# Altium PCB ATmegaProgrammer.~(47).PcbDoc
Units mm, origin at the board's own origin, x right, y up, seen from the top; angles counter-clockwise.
Board outline 54.1 x 69.09 mm, 2 copper layers (Top Layer, Bottom Layer); 9 components, 8 nets, 64 pads, 4 vias.
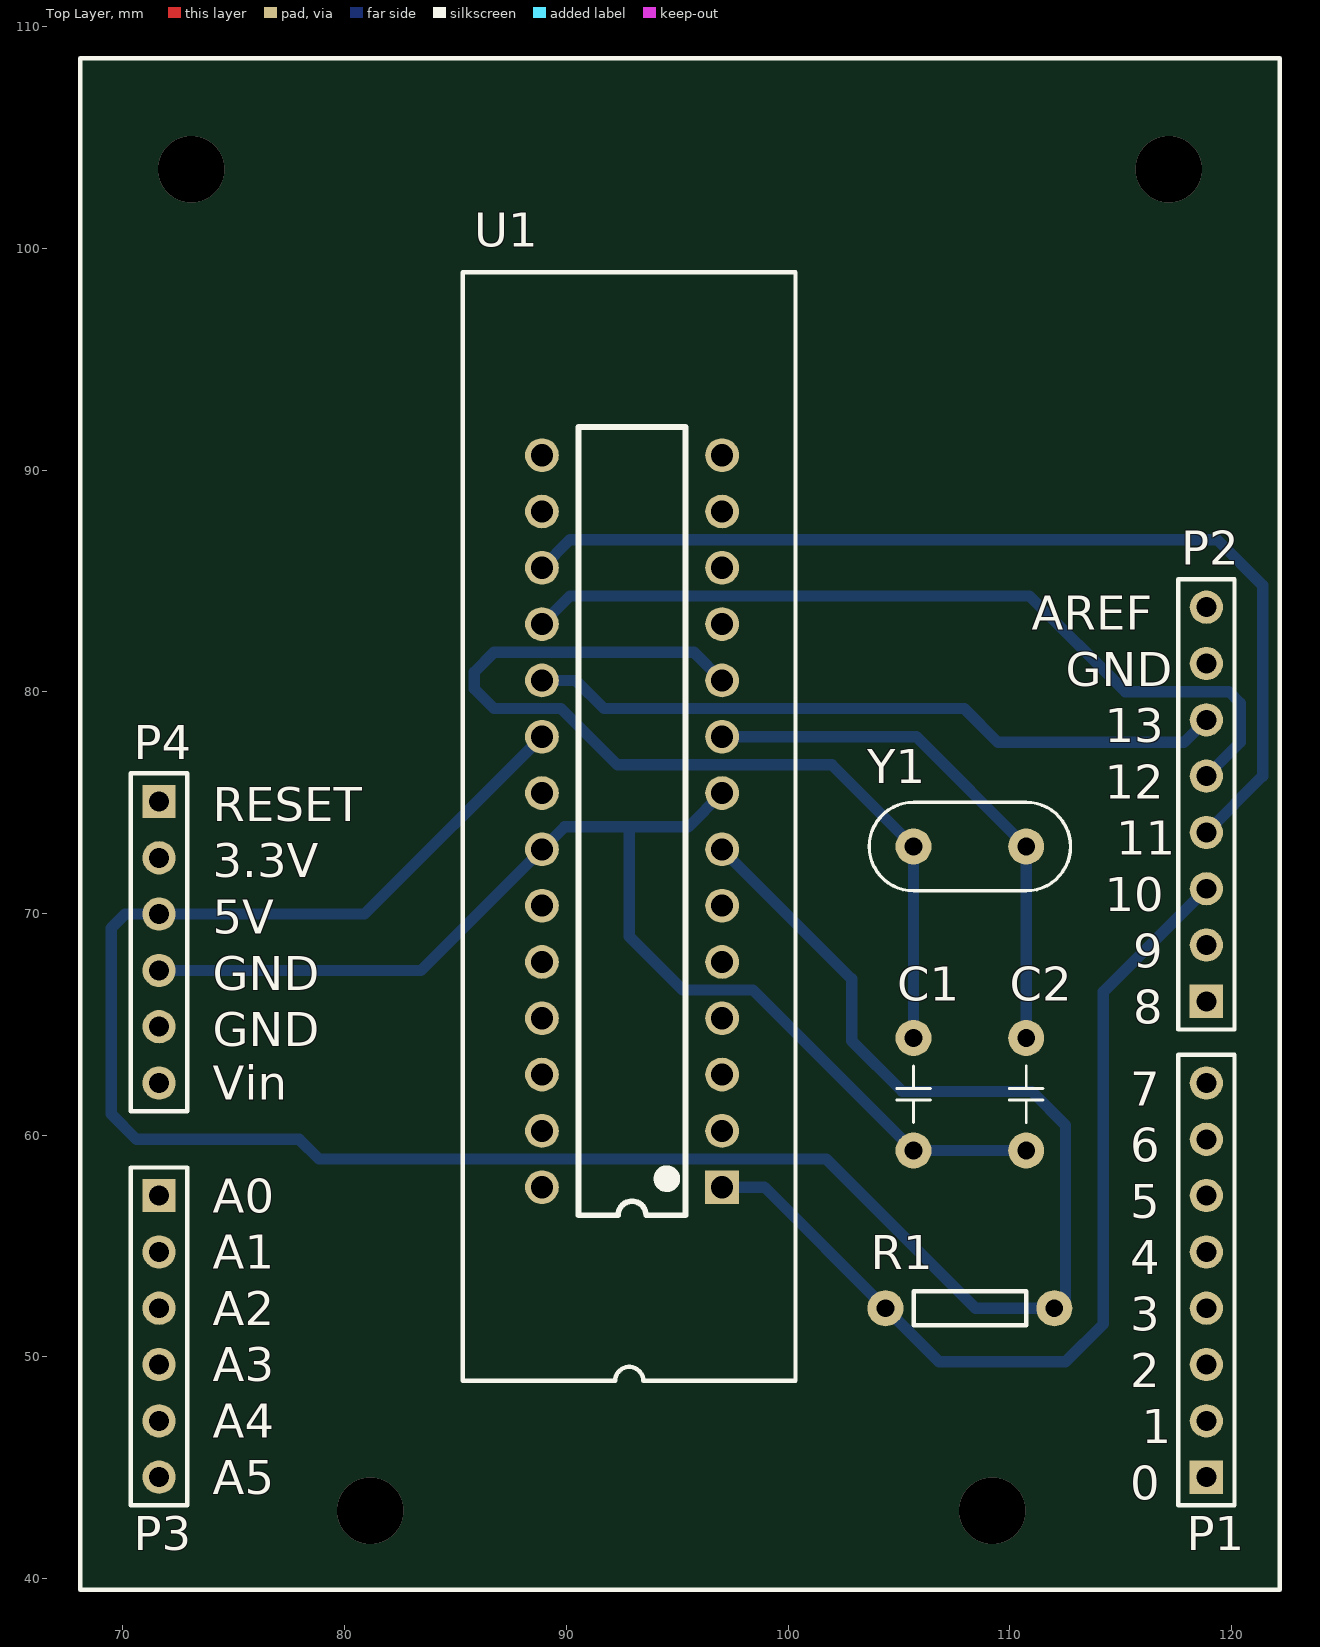
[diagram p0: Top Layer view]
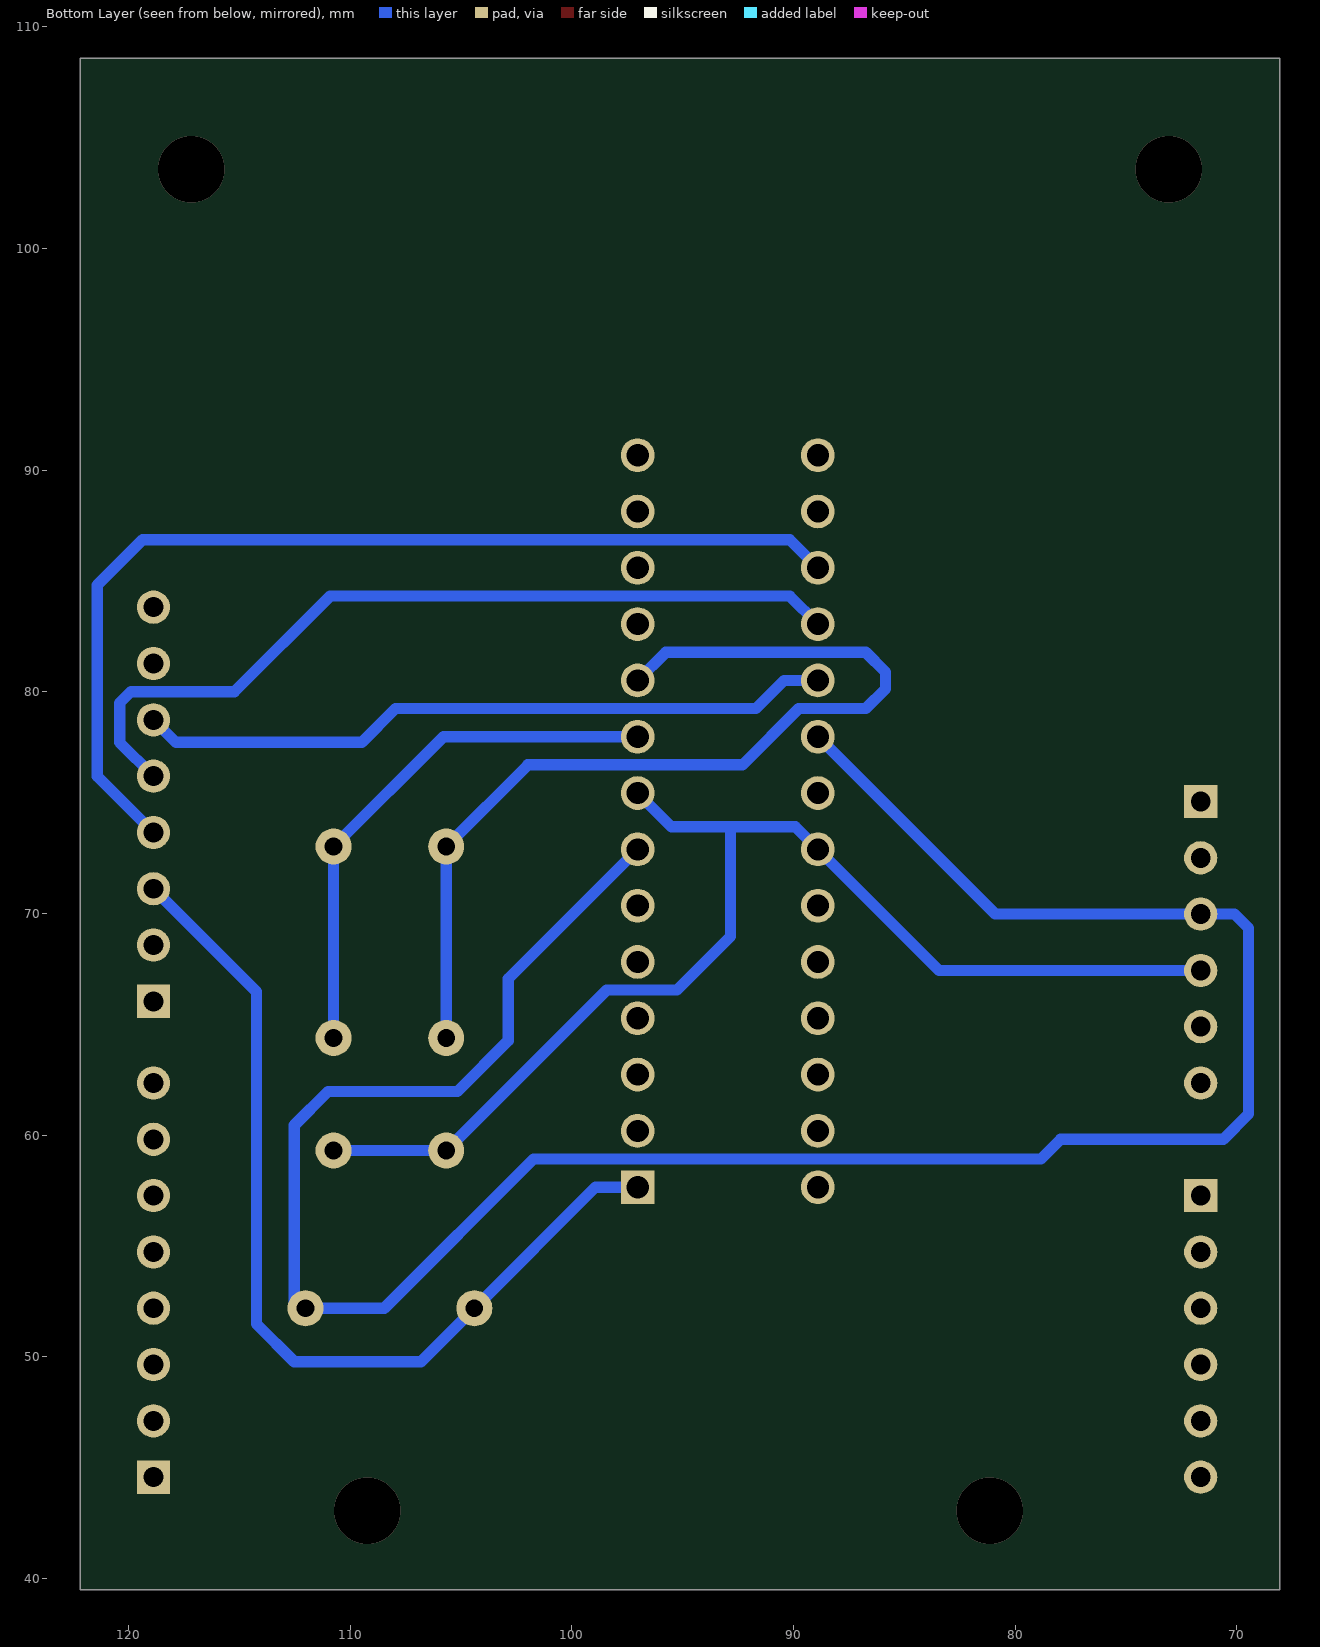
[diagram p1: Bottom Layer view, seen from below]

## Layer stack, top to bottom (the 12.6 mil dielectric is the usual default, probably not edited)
Top Layer: signal copper 0.0356
Dielectric: dielectric 0.32, FR-4, Dk 4.8
Bottom Layer: signal copper 0.0356

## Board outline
68.072,39.497 122.174,39.497 122.174,108.585 68.072,108.585

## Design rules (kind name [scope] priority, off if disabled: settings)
Clearance [All] p1: gap=0.254
PolygonConnect [All] p1: connectstyle=Relief reliefconductorwidth=0.254 reliefentries=4 polygonreliefangle="90 Angle"
RoutingLayers [All] p1: top layer_v5=FALSE bottom layer_v5=TRUE
RoutingVias [All] p1: holewidth=0.711 width=1.27 viastyle="Through Hole" minholewidth=0.711 minwidth=1.27 maxholewidth=0.711 maxwidth=1.27
SilkscreenOverComponentPads [All] p1: minsilkscreentomaskgap=0.254
SolderMaskExpansion [All] p1: expansion=0.102
Width [All] p1: maxlimit=1.016 minlimit=0.254 preferedwidth=0.508
26 further rules are at their usual default settings.

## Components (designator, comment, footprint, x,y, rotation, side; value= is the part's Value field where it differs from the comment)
C1 "20pF" C200 105.664,61.849 r180 top
C2 "20pF" C200 110.744,61.849 r180 top
P1 "Header 8" HDR1X8 118.872,44.577 r90 top
P2 "Header 8" HDR1X8 118.872,66.04 r90 top
P3 "Header 6" HDR1X6 71.628,57.277 r270 top
P4 "Header 6" HDR1X6 71.628,75.057 r270 top
R1 "10k" AXIAL-0.3 108.204,52.197 r0 top
U1 "ATmega328" "DIP28  socket" 92.964,72.136 r180 top
Y1 "16MHz" XTAL4-8 108.204,73.025 r180 top

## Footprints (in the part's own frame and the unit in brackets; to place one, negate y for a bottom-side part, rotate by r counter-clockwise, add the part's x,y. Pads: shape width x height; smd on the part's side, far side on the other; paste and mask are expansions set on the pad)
AXIAL-0.3 [mil] "0.3\" Resistor; 2 Leads"
  round 64 hole 31.5: 1(-150,0) 2(150,0)
  silkscreen extent -100,-30 100,30, body extent -161,-39 165,39, height 86
C200 [mil] "鹅溅筿甧竟"
  round 64 hole 31.5: 1(0,100) 2(0,-100)
  silkscreen extent -30,-50 30,50, body extent -41,-136 39,135, height 354
"DIP28  socket" [mil] "DIP, 28-Pin,Pitch 2.54 mm"
  rect 60x60 hole 39.37: 1(-160,570)
  round 60 hole 39.37: 2(-160,470) 3(-160,370) 4(-160,270) 5(-160,170) 6(-160,70) 7(-160,-30) 8(-160,-130) 9(-160,-230) 10(-160,-330) 11(-160,-430) 12(-160,-530) 13(-160,-630) 14(-160,-730) 15(160,-730) 16(160,-630) 17(160,-530) 18(160,-430) 19(160,-330) 20(160,-230) 21(160,-130) 22(160,-30) 23(160,70) 24(160,170) 25(160,270) 26(160,370) 27(160,470) 28(160,570)
  silkscreen extent -290,-1055 300,914, body extent -290,-1055 300,914, height 130
HDR1X6 [mm] "Connector; Header; 6 Position"
  rect 1.5x1.5 hole 0.9: 1(0,0)
  round 1.5 hole 0.9: 2(2.54,0) 3(5.08,0) 4(7.62,0) 5(10.16,0) 6(12.7,0)
  silkscreen extent -1.27,-1.27 13.97,1.27
HDR1X8 [mm] "Connector; Header; 8 Position"
  rect 1.5x1.5 hole 0.9: 1(0,0)
  round 1.5 hole 0.9: 2(2.54,0) 3(5.08,0) 4(7.62,0) 5(10.16,0) 6(12.7,0) 7(15.24,0) 8(17.78,0)
  silkscreen extent -1.27,-1.27 19.05,1.27
XTAL4-8 [mil]
  round 64 hole 31.5: 1(-100,0) 2(100,0)
  silkscreen extent -179,-79 179,79, body extent -178,-80 192,79, height 157

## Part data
C1 C2: library part Cap, "Capacitor"
P1 P2: "Header, 8-Pin"
P3 P4: "Header, 6-Pin"
R1: library part Res, "Resistor"
U1: "ATmega¨t¦C³æ´¹¤ù"
Y1: library part XTAL, "Crystal Oscillator"

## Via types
v1: diameter 3, hole 3, Top Layer to Bottom Layer, 4 vias

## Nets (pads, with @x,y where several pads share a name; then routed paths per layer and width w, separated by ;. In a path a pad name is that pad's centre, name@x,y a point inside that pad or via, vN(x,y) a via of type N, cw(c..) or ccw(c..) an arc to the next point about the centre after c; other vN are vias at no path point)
GND: C1.1 C2.1 P4.4 U1.8 U1.22 | length 55.6
  Bottom Layer w0.508: P4.4 83.439,67.437 U1.22 89.916,73.914 92.837,73.914 ; U1.8 95.504,73.914 92.837,73.914 ; C2.1 C1.1 98.425,66.548 95.25,66.548 92.837,68.961 92.837,73.914
MISO: P2.5 U1.18 | length 38
  Bottom Layer w0.508: U1.18 90.17,84.328 110.896,84.328 115.214,80.01 119.888,80.01 120.396,79.502 120.396,77.724 P2.5
MOSI: P2.4 U1.17 | length 46.1
  Bottom Layer w0.508: U1.17 90.17,86.868 119.355,86.868 121.412,84.811 121.412,76.2 P2.4
NetC1_2: C1.2 U1.10 Y1.2 | length 44.2
  Bottom Layer w0.508: U1.10 95.758,81.788 86.741,81.788 85.852,80.899 85.852,80.137 86.741,79.248 89.764,79.248 92.304,76.708 101.981,76.708 Y1.2 C1.2
NetC2_2: C2.2 U1.9 Y1.1 | length 24.4
  Bottom Layer w0.508: U1.9 105.791,77.978 Y1.1 C2.2
RESET: P2.3 R1.1 U1.1 | length 42.7
  Bottom Layer w0.508: U1.1 98.933,57.658 R1.1 106.807,49.784 112.522,49.784 114.224,51.486 114.224,66.472 P2.3
SCK: P2.6 U1.19 | length 31.6
  Bottom Layer w0.508: U1.19 90.424,80.518 91.694,79.248 107.95,79.248 109.474,77.724 117.856,77.724 P2.6
VCC: P4.3 R1.2 U1.7 U1.20 | length 108.6
  Bottom Layer w0.508: U1.20 80.899,69.977 70.104,69.977 69.469,69.342 69.469,60.96 70.612,59.817 77.953,59.817 78.842,58.928 101.727,58.928 108.458,52.197 112.522,52.197 112.522,60.452 110.998,61.976 105.156,61.976 102.87,64.262 102.87,67.056 U1.7
pads on no net: P1.1 P1.2 P1.3 P1.4 P1.5 P1.6 P1.7 P1.8 P2.1 P2.2 P2.7 P2.8 P3.1 P3.2 P3.3 P3.4 P3.5 P3.6 P4.1 P4.2 P4.5 P4.6 U1.2 U1.3 U1.4 U1.5 U1.6 U1.11 U1.12 U1.13 U1.14 U1.15 U1.16 U1.21 U1.23 U1.24 U1.25 U1.26 U1.27 U1.28
copper on no net:
  other v1: 81.153,43.053 109.22,43.053 73.072,103.585 117.174,103.585

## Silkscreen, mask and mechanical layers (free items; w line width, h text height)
Top Overlay:
  lines w0.2: 0,0 0,5.08 ; 0.508,0 0.889,0 ; 1.397,0 4.953,0 ; 70.358,57.068 70.358,57.277 ; 68.072,39.497 68.072,108.585 122.174,108.585 122.174,39.497 68.072,39.497
  text "AREF" at 110.998,82.804 h1.52
  text "GND" at 112.522,80.264 h1.52
  text "13" at 114.299,77.724 h1.52
  text "12" at 114.299,75.184 h1.52
  text "RESET" at 74.042,74.168 h1.52
  text "11" at 114.807,72.644 h1.52
  text "3.3V" at 74.042,71.628 h1.52
  text "10" at 114.299,70.104 h1.52
  text "5V" at 74.042,69.088 h1.52
  text "9" at 115.569,67.564 h1.52
  text "GND" at 74.042,66.548 h1.52
  text "8" at 115.569,65.024 h1.52
  text "GND" at 74.042,64.008 h1.52
  text "Vin" at 74.042,61.595 h1.52
  text "7" at 115.442,61.341 h1.52
  text "6" at 115.442,58.801 h1.52
  text "A0" at 74.042,56.515 h1.52
  text "5" at 115.442,56.261 h1.52
  text "A1" at 74.042,53.975 h1.52
  text "4" at 115.442,53.721 h1.52
  text "A2" at 74.042,51.435 h1.52
  text "3" at 115.442,51.181 h1.52
  text "A3" at 74.042,48.895 h1.52
  text "2" at 115.442,48.641 h1.52
  text "A4" at 74.042,46.355 h1.52
  text "1" at 115.949,46.101 h1.52
  text "A5" at 74.042,43.815 h1.52
  text "0" at 115.442,43.561 h1.52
